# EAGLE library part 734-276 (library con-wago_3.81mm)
Serie 734, Stiftleiste (für Leiterplatten) Einlötstift abgewinkelt 1 x 1 mm / Series 734, Male header (for PCBs) Angled solder pin 1 x 1 mm Polzahl / Pole No.: 16 Rastermaß / Pitch: 3.81 mm Bemessungsspannung / Rated Voltage: 160 V Nennstrom / Nominal Current: 10 A Lötstiftlänge: / Solder Pin Length: 3.8 mm Farbe / Color: orange / orange Stand: 01.01.2012. Die jeweils aktuellen Daten zu diesem Artikel finden Sie in unserem Produktkatalog, den Sie unter www.wago.com einsehen können. As of: 01/01/2012. Please find the newest data for this article in our product catalogue, which can be viewed under www.wago.com.
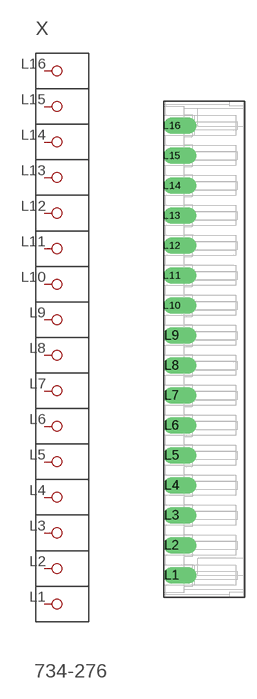
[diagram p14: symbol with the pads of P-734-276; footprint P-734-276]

Designator prefix X

## 734-276  [P-734-276]
L1  P1
L2  P2
L3  P3
L4  P4
L5  P5
L6  P6
L7  P7
L8  P8
L9  P9
L10  P10
L11  P11
L12  P12
L13  P13
L14  P14
L15  P15
L16  P16

## Footprint P-734-276 (pad centres in mm)
drill 1.4 pad 2 offset: L1 -4.15,-28.725; L2 -4.15,-24.915; L3 -4.15,-21.105; L4 -4.15,-17.295; L5 -4.15,-13.485; L6 -4.15,-9.675; L7 -4.15,-5.865; L8 -4.15,-2.055; L9 -4.15,1.755; L10 -4.15,5.565; L11 -4.15,9.375; L12 -4.15,13.185; L13 -4.15,16.995; L14 -4.15,20.805; L15 -4.15,24.615; L16 -4.15,28.425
